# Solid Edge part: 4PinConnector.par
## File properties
Author: conerly
Template: Normal.par
Last saved by: alogan
Revision: 53
Application: Solid Edge
Density: 1024.000 kg/m^3
Accuracy: 0.990
Material: ABS Plastic, high impact
Face Style: Red
Fill Style: ANSI34(Plastic)
Virtual Style: Red (Shiny)
Coef. of Thermal Exp: 9e-05
Thermal Conductivity: 0.2
Specific Heat: 0.0
Modulus of Elasticity: 1378951400.0
Poisson's Ratio: 0.4
Yield Stress: 31026406.5
Ultimate Stress: 0.0
Elongation: 0.0
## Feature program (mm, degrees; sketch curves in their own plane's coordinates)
sketch for "unnamed Protrusion 1" plane through (0, 0, 0) normal (0, 0, 1) x-axis (1, 0, 0)
  line (-37.2884, 10.9984) -> (-27.5384, 10.9984)
  line (-27.5384, 10.9984) -> (-27.5384, 20.7484)
  line (-27.5384, 20.7484) -> (-37.2884, 20.7484)
  line (-37.2884, 20.7484) -> (-37.2884, 10.9984)
  dimension (linear) = 27.5384
  dimension (linear) = 37.2884
extrude "unnamed Protrusion 1" add finite 25 along +normal
sketch for "ExtrudedProtrusion_3" plane through (-32.5384, 13.9984, 12.5) normal (0, -1, 0) x-axis (0, 0, 1)
  line (12.5, 4.75) -> (9.2, 4.75)
  line (9.2, 4.75) -> (9.2, 6.25)
  line (9.2, 6.25) -> (12.5, 4.75)
extrude "ExtrudedProtrusion_3" add finite 3.5 along -normal
sketch for "ExtrudedProtrusion_4" #1 plane through (-32.5384, 17.4984, 0) normal (0, 0, -1) x-axis (0, 1, 0)
  line (4.25, -3.75) -> (4.25, -5.75)
  line (4.25, -5.75) -> (2.25, -5.75)
  line (2.25, -3.75) -> (2.25, -5.75)
  line (4.25, -3.75) -> (2.25, -3.75)
sketch for "ExtrudedProtrusion_4" #2 plane through (-32.5384, 17.4984, 0) normal (0, 0, -1) x-axis (0, 1, 0)
  line (-5.5, -5.5) -> (-7.5, -5.5)
  line (-7.5, -5.5) -> (-7.5, -3.5)
  line (-5.5, -3.5) -> (-7.5, -3.5)
  line (-5.5, -3.5) -> (-5.5, -5.5)
sketch for "ExtrudedProtrusion_4" #3 plane through (-32.5384, 17.4984, 0) normal (0, 0, -1) x-axis (0, 1, 0)
  line (-7.5, 4) -> (-7.5, 6)
  line (-7.5, 6) -> (-5.5, 6)
  line (-5.5, 6) -> (-5.5, 4)
  line (-7.5, 4) -> (-5.5, 4)
sketch for "ExtrudedProtrusion_4" #4 plane through (-32.5384, 17.4984, 0) normal (0, 0, -1) x-axis (0, 1, 0)
  line (2.25, 6) -> (4.25, 6)
  line (4.25, 6) -> (4.25, 4)
  line (2.25, 4) -> (4.25, 4)
  line (2.25, 6) -> (2.25, 4)
  dimension (linear) = 2.25
extrude "ExtrudedProtrusion_4" add finite 12 along -normal
sketch for "ExtrudedProtrusion_5" #1 plane through (-32.2884, 17.4984, 12.5) normal (1, 0, 0) x-axis (0, -1, 0)
  line (6.5, 9.25) -> (8.75, 9.25)
  line (8.75, 9.25) -> (8.75, -1.4212)
  line (10.5, -2.3314) -> (8.75, -1.4212)
  line (10.5, -2.3314) -> (10.5, -2.9)
  line (10.5, -2.9) -> (7.5, -8.25)
  line (7.5, 6.75) -> (7.5, -8.25)
  line (6.5, 6.75) -> (7.5, 6.75)
  line (6.5, 9.25) -> (6.5, 6.75)
sketch for "ExtrudedProtrusion_5" #2 plane through (-32.2884, 17.4984, 12.5) normal (1, 0, 0) x-axis (0, -1, 0)
  line (-3.25, 9.25) -> (-5.5, 9.25)
  line (-5.5, 9.25) -> (-5.5, -1.4212)
  line (-7.25, -2.3314) -> (-5.5, -1.4212)
  line (-7.25, -2.3314) -> (-7.25, -2.9)
  line (-7.25, -2.9) -> (-4.25, -8.25)
  line (-4.25, 6.75) -> (-4.25, -8.25)
  line (-3.25, 6.75) -> (-4.25, 6.75)
  line (-3.25, 9.25) -> (-3.25, 6.75)
extrude "ExtrudedProtrusion_5" add finite 5 symmetric
sketch for "ExtrudedCutout_1" #1 plane through (-32.5384, 17.4984, 25) normal (0, 0, 1) x-axis (0, 1, 0)
  line (-1, -0.75) -> (2.5, -0.75)
  line (2.5, -0.75) -> (2.5, -4.25)
  line (2.5, -4.25) -> (-1, -4.25)
  line (-1, -4.25) -> (-1, -0.75)
sketch for "ExtrudedCutout_1" #2 plane through (-32.5384, 17.4984, 25) normal (0, 0, 1) x-axis (0, 1, 0)
  line (-1, 3.9418) -> (2.5, 3.9418)
  line (2.5, 3.9418) -> (2.5, 1.4418)
  line (2.5, 1.4418) -> (1.5, 0.4418)
  line (1.5, 0.4418) -> (0, 0.4418)
  line (0, 0.4418) -> (-1, 1.4418)
  line (-1, 1.4418) -> (-1, 3.9418)
sketch for "ExtrudedCutout_1" #3 plane through (-32.5384, 17.4984, 25) normal (0, 0, 1) x-axis (0, 1, 0)
  line (-5.5, 3.9418) -> (-2, 3.9418)
  line (-2, 3.9418) -> (-2, 0.4418)
  line (-2, 0.4418) -> (-5.5, 0.4418)
  line (-5.5, 0.4418) -> (-5.5, 3.9418)
sketch for "ExtrudedCutout_1" #4 plane through (-32.5384, 17.4984, 25) normal (0, 0, 1) x-axis (0, 1, 0)
  line (-5.5, -0.75) -> (-2, -0.75)
  line (-2, -0.75) -> (-2, -3.25)
  line (-2, -3.25) -> (-3, -4.25)
  line (-3, -4.25) -> (-4.5, -4.25)
  line (-4.5, -4.25) -> (-5.5, -3.25)
  line (-5.5, -3.25) -> (-5.5, -0.75)
  dimension (linear) = 2
  dimension (linear) = 1
  dimension (linear) = 2.5
  dimension (linear) = 2.5
  dimension (linear) = 2
extrude "ExtrudedCutout_1" cut finite 9 along -normal
sketch for "ExtrudedCutout_2" #1 plane through (-32.5384, 17.4984, 0) normal (0, 0, -1) x-axis (-1, 0, 0)
  line (3.9419, -2) -> (0.4419, -2)
  line (0.4419, -2) -> (0.4419, -5.5)
  line (0.4419, -5.5) -> (3.9419, -5.5)
  line (3.9419, -5.5) -> (3.9419, -2)
sketch for "ExtrudedCutout_2" #2 plane through (-32.5384, 17.4984, 0) normal (0, 0, -1) x-axis (-1, 0, 0)
  line (-0.75, -2) -> (-4.25, -2)
  line (-4.25, -2) -> (-4.25, -5.5)
  line (-4.25, -5.5) -> (-0.75, -5.5)
  line (-0.75, -5.5) -> (-0.75, -2)
sketch for "ExtrudedCutout_2" #3 plane through (-32.5384, 17.4984, 0) normal (0, 0, -1) x-axis (-1, 0, 0)
  line (-0.75, 2.5) -> (-4.25, 2.5)
  line (-4.25, 2.5) -> (-4.25, -1)
  line (-4.25, -1) -> (-0.75, -1)
  line (-0.75, -1) -> (-0.75, 2.5)
sketch for "ExtrudedCutout_2" #4 plane through (-32.5384, 17.4984, 0) normal (0, 0, -1) x-axis (-1, 0, 0)
  line (3.9419, 2.5) -> (0.4419, 2.5)
  line (0.4419, 2.5) -> (0.4419, -1)
  line (0.4419, -1) -> (3.9419, -1)
  line (3.9419, -1) -> (3.9419, 2.5)
extrude "ExtrudedCutout_2" cut finite 6 along -normal
sketch for "unnamed Cutout 1" #1 plane through (-34.7303, 13.7484, 6) normal (0, 0, -1) x-axis (1, 0, 0)
  circle centre (0, 0) radius 1
sketch for "unnamed Cutout 1" #2 plane through (-34.7303, 13.7484, 6) normal (0, 0, -1) x-axis (1, 0, 0)
  circle centre (4.6919, 0) radius 1
sketch for "unnamed Cutout 1" #3 plane through (-34.7303, 13.7484, 6) normal (0, 0, -1) x-axis (1, 0, 0)
  circle centre (4.6919, -4.5) radius 1
sketch for "unnamed Cutout 1" #4 plane through (-34.7303, 13.7484, 6) normal (0, 0, -1) x-axis (1, 0, 0)
  circle centre (-0.0581, -4.5) radius 1
extrude "unnamed Cutout 1" cut through along -normal
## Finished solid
Body 1: solid body, 96 faces, 246 edges, 158 vertices.
  Faces by surface: plane 92, cylinder 4
  Edges by curve: line 238, circle 8
Bounding box of the edges (mm): 12.250 x 17.750 x 25.000, from (-38.7884, 6.9984, 0) to (-26.5384, 24.7484, 25).
Cylindrical faces by radius (mm): R1 x4
Planar faces by outward normal: +x 15, +y 17, +z 11, -x 15, -y 17, -z 8, oblique 9
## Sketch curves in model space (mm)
circle centre (-30.0384, 18.2484, 6) radius 1
circle centre (-34.7884, 18.2484, 6) radius 1
circle centre (-30.0384, 13.7484, 6) radius 1
circle centre (-34.7303, 13.7484, 6) radius 1
line (-34.7303, 13.7484, 6) -> (-34.7303, 13.7484, -14.2417)
line (-30.0384, 13.7484, 6) -> (-30.0384, 13.7484, -14.2417)
line (-30.0384, 18.2484, 6) -> (-30.0384, 18.2484, -14.2417)
line (-34.7303, 18.2484, 6) -> (-34.7303, 18.2484, -14.2417)
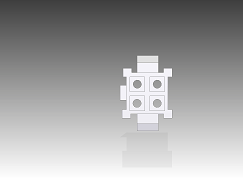
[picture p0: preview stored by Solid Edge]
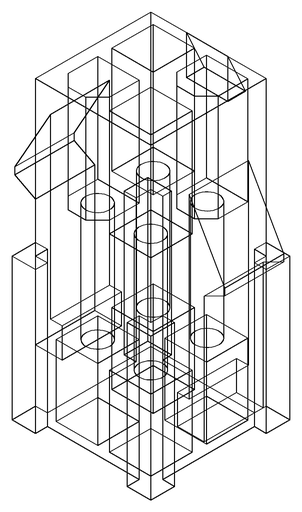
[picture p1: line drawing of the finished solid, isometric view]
